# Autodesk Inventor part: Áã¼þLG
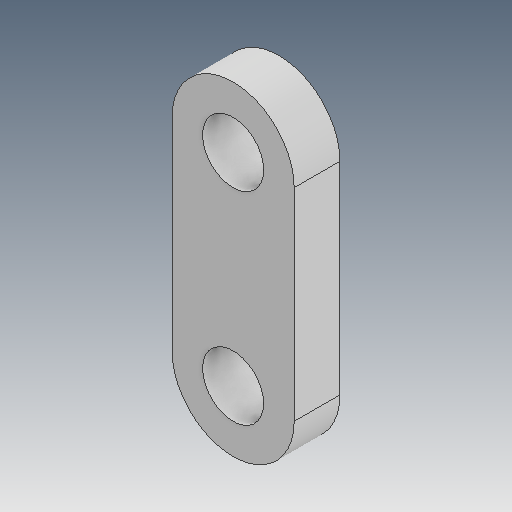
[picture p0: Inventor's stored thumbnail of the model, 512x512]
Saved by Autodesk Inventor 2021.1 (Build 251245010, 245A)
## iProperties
Created: 2019-04
Part Number: Áã¼þLG
Material: Ogólny
Document SubType Name: Modeling
Designer: user
Density: 1 g/cm^3
Appearance: Domyślna
Author: user
Revision Number: ÈÎºÎ
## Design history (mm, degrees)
feature "ÊäÈë1"
node "Bryła1"
